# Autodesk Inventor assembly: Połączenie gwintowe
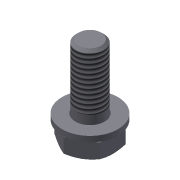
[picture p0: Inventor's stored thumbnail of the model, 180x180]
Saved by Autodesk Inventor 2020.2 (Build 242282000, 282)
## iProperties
Created: 2010-09
Part Number: Połączenie gwintowe
Document SubType Name: Assembly
Designer: F.Stasiak
ClientObjectVersion: 1
Manager: www.cadconsulting.pl
Company: Fabian Stasiak CAD Consulting
Author: F.Stasiak
Subject: Zbiór ćwiczeń. Autodesk Inventor 2020. Kurs podstawowy
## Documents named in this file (3)
- C:\2020_Kurs_podstawowy\R9 Zarządzanie plikami\369-000\Design Accelerator\Połączenie gwintowe4.iam
- C:\2020_Kurs_podstawowy\Zasoby\Content Center Files\pl-PL\ISO 7089\ISO 7089 - 8 - 140 HV(1).ipt
- C:\2020_Kurs_podstawowy\Zasoby\Content Center Files\pl-PL\ISO 4017(1)\ISO 4017 - M8 x 20ISO.ipt
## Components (2 placed, 2 different names)
1. ISO 7089 8 - 140 HV:1
2. ISO 4017 M8 x 20:1
